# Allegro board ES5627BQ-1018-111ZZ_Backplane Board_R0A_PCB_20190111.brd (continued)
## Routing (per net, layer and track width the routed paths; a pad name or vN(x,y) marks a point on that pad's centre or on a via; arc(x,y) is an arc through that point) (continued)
FAN_VP12: length 13.2
  TOP w0.381: CB7.1 67.17,24.88 67.18,24.89 ; 67.18,23.88 67.17,23.86 CB14.1
  BOTTOM w0.381: v1(68.58,25.26) 68.58,25.3 68.83,25.56 CB13.1 ; 64.39,22.72 64.21,22.9 CB10.2 ; C37.2 65.79,25.51 65.66,25.38 ; 58.67,20.68 58.29,21.07 C41.2 ; CB9.2 59.31,20.81 ; CB11.2 60.33,20.68 ; CB16.1 67.82,25.51 67.94,25.38 ; CB8.2 61.34,20.68 ; v1(66.67,19.54) 66.8,19.41 CB15.1 ; C38.2 C39.2 64.77,25.51 ; CB12.2 62.36,20.68 ; CB17.1 66.8,25.38 ; C40.2 64.77,26.53
  vias: v1(63.88,19.54) v1(64.39,20.18) v1(64.77,19.54) v1(65.28,20.18) v1(65.66,19.54) v1(66.42,20.18) v1(67.18,20.18) v1(67.56,22.84) v1(67.69,19.54) v1(67.82,23.99) v1(67.94,24.75) v1(68.2,20.18) v1(68.33,23.35) v1(68.45,22.46) v1(68.71,24.24) v1(68.71,19.54) v1(69.22,23.35) v1(69.34,25.26) v1(69.34,22.46) v1(69.34,20.18) v1(69.47,24.24) v2(59.94,17.89) v2(63.5,20.68) v2(64.94,22.2) v2(66.54,21.16) v2(68.96,21.32)
FAN_VP12_R: length 5.9
  TOP w0.381: C49.2 84.26,26.53 R63.1
  BOTTOM w0.127: v2(82.17,26.53) 81.86,26.22 v1(81.86,25.71)
  BOTTOM w0.381: v1(81.86,25.71) C76.1 82.45,25 82.51,25.06 U3.6
FB_3P3_1P8: length 5.2
  TOP w0.127: v1(21.34,27.03) 21.46,27.03 21.72,27.29 R43.2
  TOP w0.381: U2.8 22.05,25.71 R45.2 R43.2
  BOTTOM w0.127: v2(21.08,26.15) 21.08,26.78 v1(21.34,27.03)
HGATE_MB1: length 11
  TOP w0.381: Q11.4 v1(83.69,14.13)
  BOTTOM w0.127: v2(83.19,13.45) 83.19,13.62 v1(83.69,14.13)
  BOTTOM w0.381: R68.2 81.21,21.52 81.41,21.32 81.83,21.32 83.5,19.65 83.5,15.67 83.19,15.35 83.19,14.64 v1(83.69,14.13)
HOLE_2: length 17.6
  BOTTOM w0.127: 61.59,3.03 60.58,2.02 60.21,2.02 v2(58.8,3.43)
  BOTTOM w0.381: 65.15,5.06 C68.1 C48.1 ; H3.7 65.21,4.05 C48.1 ; C48.1 61.29,3.34 61.59,3.03 65.41,3.03
HOLE_3: length 23.7
  TOP w0.381: 98.93,19.41 99.15,19.63 99.15,22.63 98.88,22.9 C31.1 ; 96.52,19.29 96.32,19.49 96.32,22.64 96.59,22.91 C36.1 ; C36.1 97.24,19.69 H1.1 98.3,19.83 C31.1 ; C36.1 97.26,22.9 C31.1
  BOTTOM w0.381: v2(93.5,23.6) 93.5,23.59 93.85,23.24 93.85,20.45 H1.8
HOLE_5: length 24.4
  TOP w0.381: H2.7 48.14,25.13 44.83,25.13 44.52,25.44 C33.1 48.39,26.02 ; H2.8 48.87,27.03 C35.1 44.52,27.62 44.79,27.89 49.19,27.89 49.4,27.67
  BOTTOM w0.381: H2.7 47.77,24.49 v2(42.67,24.49)
HOLE_6: length 23.7
  TOP w0.381: C69.1 5.08,9.9 H4.5 6.08,10.33 C58.1 ; C69.1 4.48,7.04 4.06,7.46 4.06,10.14 4.57,10.65 ; C69.1 6.07,7.04 C58.1 ; 6.86,10.65 7.11,10.4 7.11,7.35 6.81,7.05 C58.1
  BOTTOM w0.381: 8.51,11.67 8.89,11.67 v2(12.83,7.73)
RESERVED_1: length 5.9
  TOP w0.127: U1.A2 v1(44.83,19.56) 45.16,19.56 R28.1
  BOTTOM w0.127: v2(43.94,19.92) 44.3,19.56 v1(44.83,19.56)
RESERVED_2: length 6.4
  TOP w0.127: R29.1 45.61,19.03 v1(44.69,18.11) 41.55,18.11 U1.A4
  BOTTOM w0.127: v1(44.69,18.11) 45.05,18.11 v2(45.59,18.65)
RESERVED_3: length 6.5
  TOP w0.127: R30.1 44.72,17.09 v1(44.69,17.09) 41.53,17.09 U1.A5
  BOTTOM w0.127: v2(43.69,17.76) 44.36,17.09 v1(44.69,17.09)
RESERVED_4: length 6.3
  TOP w0.127: R31.1 45.61,17 v1(44.69,16.08) 41.52,16.08 U1.A6
  BOTTOM w0.127: v1(44.69,16.08) 45.31,16.08 v2(45.59,16.37)
RESERVED_5: length 6.6
  TOP w0.127: R32.1 45.65,15.47 45.24,15.06 v1(44.69,15.06) 41.5,15.06 U1.A7
  BOTTOM w0.127: v2(43.81,15.48) 44.23,15.06 v1(44.69,15.06)
SENSE_12V: length 2
  BOTTOM w0.381: U3.5 v1(82.68,24.11) ; 78.49,20.68 78.44,20.74 C44.1
  vias: v1(79.25,19.29) v1(79.25,18.27) v1(79.25,17.26) v1(79.25,16.11) v1(80.39,19.29) v1(80.39,18.27) v1(80.39,17.26) v1(80.39,16.11) v1(81.79,19.29) v1(81.79,18.27) v1(81.79,17.26) v1(81.79,16.11) v1(82.93,19.29) v1(82.93,18.27) v1(82.93,17.26) v1(82.93,16.11) v2(80.77,14.97)
VERSION_ID_1: length 6.2
  TOP w0.127: U1.T6 v1(25.27,15.56)
  BOTTOM w0.127: v2(21.34,13.7) 24,13.7 24.2,13.9 R53.2 R52.1 24.76,15.22 25.1,15.56 v1(25.27,15.56)
VERSION_ID_2: length 6.9
  TOP w0.127: U1.T7 v1(25.27,14.56)
  BOTTOM w0.127: v1(25.27,14.56) 25.1,14.56 24.77,14.23 24.77,13.57 24.38,13.19 R51.1 R50.2 24.2,11.87 24,11.67 21.59,11.67 v2(21.46,11.79)
VERSION_ID_3: length 8.1
  TOP w0.127: U1.T8 v1(25.27,13.56)
  BOTTOM w0.127: v2(21.72,9.38) 24,9.38 24.2,9.58 R49.2 R48.1 24.77,11.16 25.15,11.54 25.15,13.44 v1(25.27,13.56)
N65528284: length 3.1
  BOTTOM w0.127: v2(88.01,26.4) 88.14,26.27 C77.1 87.87,25.06 U3.1
N65531777: length 5.5
  BOTTOM w0.127: v2(90.42,23.63) 90.2,23.85 88.53,23.85 88.44,23.94 88.4,23.97 88.4,23.97 88.14,24.24 ; 88.14,24.24 R69.1 88.03,23.16 U3.3 ; 88.14,24.24 R65.1
N65532055: length 2.2
  BOTTOM w0.127: R67.2 C78.2 80.08,22.03 v2(80.01,21.95)
N65533374: length 4
  BOTTOM w0.127: R67.1 82.12,23.66 v2(81.79,23.99) ; R67.1 82.31,23.16 U3.4 ; R67.1 R68.1

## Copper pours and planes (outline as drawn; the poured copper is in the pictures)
12V_FAN on TOP: 81.92,14.72 78.11,14.72 77.6,15.22 77.6,18.53 76.96,19.16 76.2,19.16 75.95,18.91 75.95,12.43 74.42,10.91 74.42,7.11 74.8,6.73 83.69,6.73 84.45,7.49 84.45,9.64 82.3,11.79 82.3,14.33
GND on TOP: 72.14,20.05 72.14,17.26 72.01,17.13 72.01,13.95 72.77,13.19 74.3,13.19 74.55,13.45 74.55,18.91 76.58,20.94 76.58,28.05 76.45,28.18 73.66,28.18 73.41,27.92 73.41,21.19 72.77,20.56 72.64,20.56
GND on TOP: 60.83,10.27 60.58,10.52 60.58,19.67 61.21,20.3 62.48,20.3 63.37,21.19 63.37,22.72 63.63,22.97 63.25,23.35 63.25,26.15 61.98,27.42 61.21,27.42 60.96,27.67 60.96,28.18 61.21,28.43 64.39,28.43 64.9,27.92 64.9,25.64 65.15,25.38 65.79,25.38 65.91,25.26 65.91,21.45 65.53,21.07 64.26,21.07 62.61,19.41 62.61,10.4 62.48,10.27
GND on BOTTOM: 61.59,28.43 79.88,28.43 81.41,26.91 81.41,24.49 80.77,23.86 80.14,23.86 79.5,23.22 79.5,22.84 78.87,22.21 78.36,22.21 77.09,20.94 77.09,20.3 76.83,20.05 76.58,20.05 76.45,19.92 76.45,19.16 75.44,18.14 75.44,17 76.45,15.99 76.45,14.59 75.56,13.7 61.72,13.7 61.47,13.95 61.47,15.99 61.59,16.11 65.79,16.11 66.55,16.87 66.55,17.51 66.67,17.64 71.25,17.64 72.9,19.29 72.9,25.76 71.75,26.91 64.52,26.91 64.01,27.42 61.21,27.42 61.21,28.05
GND on BOTTOM: 16.13,25.38 19.81,25.38 20.32,24.88 20.32,22.08 20.07,21.83 20.07,20.43 19.68,20.05 16.51,20.05 15.88,20.68 15.88,25.13
GND on G2: 2.16,1.02 102.69,1.02 102.69,28.98 2.16,28.98
FAN_1V8 on TOP: 19.94,24.75 22.61,24.75 23.11,24.24 23.11,21.07 22.48,20.43 20.32,20.43 19.68,21.07 19.68,24.49
FAN_1V8 on BOTTOM: 20.7,24.88 22.86,24.88 23.24,25.26 23.88,25.26 25.15,23.99 25.15,22.97 22.73,20.56 20.95,20.56 20.7,20.81
FAN_1V8 on V3: 24,25.51 22.23,25.51 21.34,24.62 21.34,22.08 22.48,20.94 24.26,20.94 25.53,19.67 25.53,15.1 27.05,13.57 31.5,13.57 31.62,13.45 31.62,12.05 32.89,10.78 34.92,10.78 35.43,11.29 35.43,13.95 33.78,15.6 29.34,15.6 27.88,17.06 27.88,21.38 24.38,24.88 24.38,25.13
FAN_VP3P3 on TOP: 59.18,10.4 60.07,10.4 60.33,10.65 60.33,20.3 60.96,20.94 62.23,20.94 62.61,21.32 62.61,26.27 61.72,27.16 59.05,27.16 58.93,27.03 58.93,20.56 59.05,20.43 59.05,10.52
FAN_VP3P3 on TOP: 12.19,24.37 12.19,22.34 11.94,22.08 11.94,21.32 12.32,20.94 15.62,20.94 16.13,21.45 16.13,23.35 16,23.48 14.1,23.48 13.46,24.11 13.46,24.49 13.34,24.62 12.45,24.62
FAN_VP3P3 on BOTTOM: 62.61,27.16 60.45,27.16 57.78,24.49 57.78,22.97 57.91,22.84 62.36,22.84 62.87,23.35 62.87,26.91
FAN_VP3P3 on V3: 2.67,28.48 102.18,28.48 102.18,1.52 2.67,1.52
FAN_VP12 on TOP: 72.52,27.67 67.06,27.67 66.67,27.29 66.67,21.45 66.17,20.94 64.52,20.94 63.12,19.54 63.12,10.4 63.25,10.27 70.23,10.27 71.63,11.67 71.63,20.94 72.64,21.95 72.64,27.54
FAN_VP12 on BOTTOM: 64.9,27.16 64.26,27.16 64.64,26.78 64.64,23.73 64.01,23.1 63.5,23.1 62.87,22.46 62.87,21.19 62.74,21.07 58.29,21.07 58.17,20.94 58.17,20.81 58.74,20.24 58.74,17.83 59.44,17.13 65.79,17.13 66.8,18.14 70.61,18.14 71.88,19.41 71.88,25.64 71.12,26.4 65.28,26.4 64.9,26.78
FAN_VP12_R on TOP: 77.09,22.08 77.09,28.43 77.6,28.94 84.45,28.94 84.84,28.56 84.84,25.38 84.45,25 81.66,25 80.9,24.24 80.9,21.95 80.77,21.83 77.34,21.83
HOLE_2 on TOP (solid shape): outline of 235 points within 64.4,0.48 71.41,7.49
HOLE_2 on BOTTOM (solid shape): outline of 235 points within 64.4,0.48 71.41,7.49
HOLE_3 on TOP (solid shape): outline of 235 points within 94.2,13.1 101.21,20.11
HOLE_3 on BOTTOM (solid shape): outline of 235 points within 94.2,13.1 101.21,20.11
HOLE_5 on TOP (solid shape): outline of 235 points within 47.4,21.5 54.41,28.5
HOLE_5 on BOTTOM (solid shape): outline of 235 points within 47.4,21.5 54.41,28.5
HOLE_6 on TOP (solid shape): outline of 235 points within 2.29,9.74 9.3,16.75
HOLE_6 on BOTTOM (solid shape): outline of 235 points within 2.29,9.74 9.3,16.75
SENSE_12V on TOP: 78.49,20.56 78.49,15.6 78.74,15.35 83.57,15.35 83.69,15.48 83.69,18.78 85.22,20.3 85.22,23.61 84.33,24.49 81.92,24.49 81.41,23.99 81.41,21.95 80.77,21.32 79.25,21.32
SENSE_12V on BOTTOM: 77.6,21.07 82.42,21.07 83.31,20.18 83.31,15.22 82.55,14.46 77.72,14.46 77.22,14.97 77.22,16.24 76.96,16.49 76.58,16.49 76.45,16.62 76.45,18.27 76.96,18.78 76.96,19.67 77.6,20.3

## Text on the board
Ref Des/Assembly Top: P\N:142000002197H REV:0A
PAGE_OUTLINE: LinJing | 20181218 | 1 | ZONE | ROUGHNESS | ANGLE | PART NO. | MATERIAL | DESIGN | SCALE | UNIT | DIM. | 500 | 250 | 63 | 16 | 0 | GRADE | 1000 | 0.1 | 0.05 | . | 0.15 | 0.2 | 0.25 | 0.3 | 2 | 0.5 | 3 | 0.4 | 0.6 | 0.8 | 4 | 1.2 | 5 | 1.8 | 3.0 | FINISH. | MM | [IN] | This document and the | technical data disclosed | are proprietary to Accton | Tech. Corp. and shall not be | duplicated, used, released, | or disclosed without | expressed written permission. | OUTLINE-Corient_BACK-PANEL | Reason | DESCRIPTION | UNSPECIFIED | TOL'S (+/-   mm) | +/- | DWG. TITLE | SHEET  / | REV. | SIZE | FMA-MD01001-02 R02 | 1deg | TECHNOLOGY CORP. | PCB T=1.6mm | A0 | A3 | 30 [1.181] | ∅3.1 [∅0.122] | 103.7 [4.083] | ∅7 [∅0.276] | ∅3 [∅0.118] | ∅9 [∅0.354]
User.5: TOP | 1
User.6: G2 | 2
User.7: V3 | 3
User.8: BOT | 4
User.9: SST | 5
User.10: SSB | 6
User.11: SMT | 7
User.12: SMB | 8
User.13: PMT | 9
User.14: PMB | 10
User.15: DRILL | 11
User.16: DIM | 12
User.17: FIGURE | SIZE | 10.0 | 12.0 | 30.0 | 40.0 | 47.0 | 122.0 | 138.0 | DRILL CHART: TOP to BOTTOM | ALL UNITS ARE IN MILS | TOLERANCE | +3.0/-3.0 | +2.0/-2.0 | PLATED | NON-PLATED | QTY | 309 | 32 | 20 | 8 | 2 | 4
